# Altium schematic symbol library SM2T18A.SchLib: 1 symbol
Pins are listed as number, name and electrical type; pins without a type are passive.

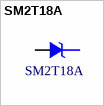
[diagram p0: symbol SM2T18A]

## SM2T18A
designator D?
footprint ST_DO-216AA
footprint PCBComponent_1
pins: 1 A, 2 K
